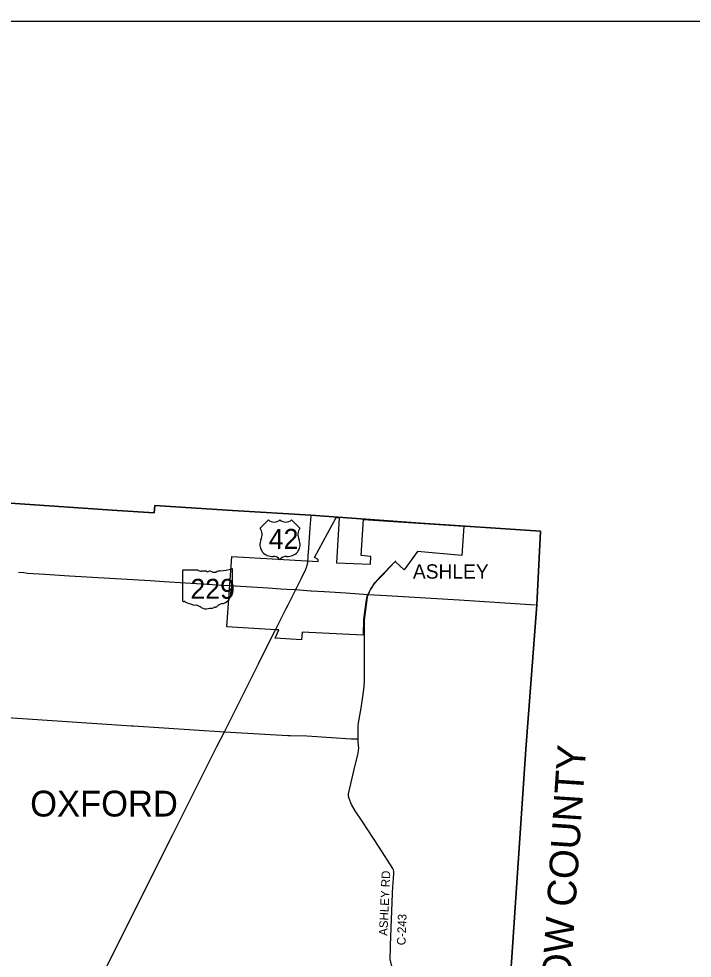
# Model space of a CAD drawing. Extents: x 1674899 to 2057726, y 653888 to 988278.
# Drawn here: x 1831966 to 1855438, y 864966 to 897723 of the extents above; entities that cross this region are included whole.
import ezdxf

# ---------------------------------------------------------------- set-up
doc = ezdxf.new("R2010")
doc.units = 0
for name, color, linetype in [('GM_X_Adjacent_County', 7, 'Continuous'), ('GM_X_Adjacent_County_Text', 7, 'Continuous'), ('GM_X_Corporation', 7, 'Continuous'), ('GM_X_Corporation_Text', 7, 'Continuous'), ('GM_X_County', 7, 'Continuous'), ('GM_X_County_Road', 7, 'Continuous'), ('GM_X_County_Road_Text', 7, 'Continuous'), ('GM_X_State_Location', 7, 'Continuous'), ('GM_X_State_Route', 7, 'Continuous'), ('GM_X_State_Shield', 7, 'Continuous'), ('GM_X_Township', 7, 'Continuous'), ('GM_X_Township_Text', 7, 'Continuous'), ('GM_X_US_Location', 7, 'Continuous'), ('GM_X_US_Route', 7, 'Continuous'), ('GM_X_US_Shield', 7, 'Continuous'), ('SH_Data', 7, 'Continuous'), ('SH_Named_Boundary', 7, 'Continuous')]:
    doc.layers.add(name, color=color, linetype=linetype)

msp = doc.modelspace()

# ---------------------------------------------------------------- linework, layer by layer
at = {"layer": 'GM_X_Adjacent_County'}
msp.add_lwpolyline([(1849106, 864311), (1849634, 872258), (1850017, 877290), (1850147, 879854), (1845959, 880135), (1842150, 880416), (1839410, 880574), (1836708, 880754), (1836682, 880495), (1835395, 880574), (1829123, 881005), (1828513, 881052), (1826517, 881205), (1823082, 881429), (1823458, 886911), (1823627, 889370), (1824025, 895167), (1824431, 901093)], dxfattribs=at)
at = {"layer": 'GM_X_Corporation'}
msp.add_lwpolyline([(1839212, 876522), (1839395, 878979), (1842403, 878797), (1842406, 878874), (1842276, 878944), (1843026, 880333), (1843137, 880326), (1843037, 878758), (1844222, 878701), (1844237, 878976), (1843894, 879006), (1843983, 880269), (1847478, 880034), (1847407, 879013), (1845866, 879149), (1845394, 878513), (1845080, 878796), (1844533, 878238), (1844393, 878064), (1844314, 877970), (1844271, 877898), (1844236, 877846), (1844178, 877730), (1844140, 877653), (1844101, 877578), (1844075, 877468), (1843989, 876865), (1843985, 876781), (1843972, 876227), (1841843, 876336), (1841816, 876073), (1840902, 876121), (1841027, 876414), (1840914, 876421)], close=True, dxfattribs=at)
at = {"layer": 'GM_X_County'}
msp.add_lwpolyline([(1809339, 887629), (1813443, 887429), (1813717, 887422), (1814360, 887388), (1814847, 887358), (1815353, 887328), (1818316, 887169), (1823458, 886911), (1823082, 881429), (1826517, 881205), (1828513, 881052), (1829123, 881005), (1835395, 880574), (1836682, 880495), (1836708, 880754), (1839410, 880574), (1842150, 880416), (1845959, 880135), (1850147, 879854), (1850017, 877290), (1849634, 872258), (1849106, 864311)], dxfattribs=at)
at = {"layer": 'GM_X_County_Road'}
for points in [[(1844140, 877653), (1844178, 877730), (1844236, 877846), (1844271, 877898), (1844314, 877970), (1844393, 878064), (1844672, 878363), (1844876, 878580), (1845108, 878825)], [(1844920, 865421), (1844988, 867215), (1844990, 867274), (1845035, 867925), (1845034, 867981), (1845022, 868042), (1845000, 868095), (1844527, 868834), (1843932, 869740), (1843693, 870106), (1843565, 870325), (1843478, 870530), (1843453, 870621), (1843455, 870702), (1843691, 871703), (1843783, 872054), (1843799, 872125), (1843808, 872218), (1843813, 872294), (1843800, 872513), (1843796, 872610), (1843794, 872719), (1843797, 872872), (1843799, 873058), (1843810, 873171), (1843903, 873683), (1843995, 874339), (1844011, 874603), (1844010, 875790), (1844011, 876128), (1844012, 876758), (1844119, 877561), (1844140, 877653)], [(1825350, 873697), (1828404, 873550), (1830426, 873436), (1830706, 873421), (1835899, 873073), (1835968, 873069), (1839135, 872864)], [(1839135, 872864), (1839344, 872852), (1841345, 872730), (1841421, 872727), (1842003, 872716), (1842870, 872667), (1843552, 872620), (1843796, 872610)], [(1848869, 860822), (1848289, 861017), (1848127, 861070), (1847820, 861177), (1847644, 861252), (1847581, 861290), (1847540, 861317), (1847370, 861450), (1845855, 862679), (1845795, 862727), (1845378, 863132), (1845338, 863172), (1845282, 863256), (1845130, 864033), (1845116, 864109), (1844927, 864878), (1844914, 864930), (1844919, 865353), (1844920, 865421)]]:
    msp.add_lwpolyline(points, dxfattribs=at)
at = {"layer": 'GM_X_State_Route'}
for points in [[(1831957, 878431), (1832136, 878410), (1832267, 878397), (1832870, 878356), (1833733, 878300), (1836550, 878131), (1837033, 878098), (1838904, 877988), (1839306, 877964)], [(1839306, 877964), (1840655, 877877), (1841096, 877846), (1841303, 877834)], [(1841303, 877834), (1841619, 877817)], [(1841619, 877817), (1842011, 877788), (1842144, 877781)], [(1842144, 877781), (1842167, 877780), (1842611, 877751), (1842621, 877751), (1843359, 877702), (1844140, 877653)], [(1844140, 877653), (1844783, 877609), (1847310, 877457), (1849978, 877293)]]:
    msp.add_lwpolyline(points, dxfattribs=at)
at = {"layer": 'GM_X_State_Shield'}
for p, q in [((1837677, 878480), (1837677, 877424)), ((1838204, 878499), (1837694, 878499)), ((1839417, 877972), (1839417, 878525)), ((1839417, 877972), (1839417, 877972))]:
    msp.add_line(p, q, dxfattribs=at)
for centre, major_axis, start_param, end_param in [((1838797, 879939), (1845, 0), 4.814394, 5.042369), ((1839398, 878527), (19.4, 0), 6.141152, 7.989035), ((1837697, 878483), (20.2, 0), 1.712693, 3.28349), ((1838325, 878621), (196, 0), 4.042523, 4.731795), ((1838390, 877905), (702, 0), 1.404758, 1.657858), ((1838549, 878488), (56.4, 0), 3.836095, 5.185415), ((1838632, 878366), (117, 0), 0.950623, 2.079405), ((1838783, 878534), (141, 0), 4.081561, 5.145723), ((1839032, 878176), (371, 0), 1.699011, 2.107814), ((1839413, 877931), (30, 0), 1.883978, 3.671073), ((1839222, 877862), (180, 0), 5.934695, 6.695948), ((1839396, 877970), (20.7, 0), 5.05454, 6.418171), ((1838900, 877670), (462, 0), 5.101752, 6.440018), ((1839486, 877741), (131, 0), 2.387724, 3.262537), ((1837697, 877421), (20.3, 0), 3.00124, 4.508301), ((1837700, 877530), (155, 0), 4.665946, 4.897461), ((1837732, 877363), (56, 0), 0.519207, 1.627899), ((1838438, 878312), (1333, 0), 4.195997, 4.488961), ((1838041, 876949), (417, 0), 0.823519, 1.323587), ((1838775, 877321), (149, 0), 4.937069, 5.64225), ((1839095, 877127), (253, 0), 1.647645, 2.488434), ((1838492, 877358), (265, 0), 4.026481, 4.996735), ((1838645, 876992), (217, 0), 1.495662, 1.94098), ((1838664, 877278), (141, 0), 4.691044, 5.507374), ((1838792, 877176), (39.7, 0), 1.147584, 2.315152)]:
    msp.add_ellipse(centre, major_axis=major_axis, ratio=0.8, start_param=start_param, end_param=end_param, dxfattribs=at)
at = {"layer": 'GM_X_Township'}
msp.add_lwpolyline([(1821956, 864281), (1822382, 871013), (1822583, 873901), (1822822, 877662), (1822932, 879384), (1823026, 880489), (1823082, 881429), (1826517, 881205), (1828513, 881052), (1829123, 881005), (1835395, 880574), (1836682, 880495), (1836708, 880754), (1839410, 880574), (1842150, 880416), (1845959, 880135), (1850147, 879854), (1850017, 877290), (1849634, 872258), (1849106, 864311)], dxfattribs=at)
at = {"layer": 'GM_X_US_Route'}
for points in [[(1842050, 878929), (1842054, 878989), (1842074, 879275), (1842125, 879970), (1842151, 880391)], [(1842000, 878620), (1842005, 878635), (1842013, 878659), (1842035, 878764), (1842042, 878816), (1842050, 878929)], [(1841619, 877817), (1841815, 878219), (1841969, 878528), (1842000, 878620)], [(1841285, 877158), (1841355, 877293), (1841619, 877817)], [(1840905, 876404), (1840914, 876421), (1841039, 876677), (1841285, 877158)], [(1832814, 860270), (1833045, 860728), (1833707, 862039), (1833995, 862623), (1834269, 863162), (1835215, 865051), (1835681, 865996), (1836078, 866774), (1836442, 867502), (1837331, 869279), (1837642, 869882), (1838022, 870648), (1838475, 871555), (1838873, 872351), (1839135, 872864), (1840316, 875226), (1840905, 876404)]]:
    msp.add_lwpolyline(points, dxfattribs=at)
at = {"layer": 'GM_X_US_Shield'}
for p, q in [((1840664, 880255), (1840374, 879965)), ((1841766, 879965), (1841476, 880255)), ((1840780, 878979), (1840838, 878979)), ((1841302, 878979), (1841360, 878979))]:
    msp.add_line(p, q, dxfattribs=at)
for centre, radius, start, end in [((1840867, 880462), 290, 225.573, 314.427), ((1841273, 880462), 290, 225.573, 314.427), ((1840041, 879732), 406, 334.5471, 35.0009), ((1842099, 879732), 406, 144.9991, 205.4529), ((1840775, 879385), 406, 154.8319, 270.6383), ((1841365, 879385), 406, 269.3617, 25.1681), ((1840838, 878689), 290, 36.8699, 90), ((1841302, 878689), 290, 90, 143.1301)]:
    msp.add_arc(centre, radius, start, end, dxfattribs=at)
at = {"layer": 'SH_Data'}
for points in [[(1842050, 878929), (1842054, 878989), (1842074, 879275), (1842125, 879970), (1842151, 880391)], [(1842000, 878620), (1842005, 878635), (1842013, 878659), (1842035, 878764), (1842042, 878816), (1842050, 878929)], [(1841619, 877817), (1841815, 878219), (1841969, 878528), (1842000, 878620)], [(1841285, 877158), (1841355, 877293), (1841619, 877817)], [(1840905, 876404), (1840914, 876421), (1841039, 876677), (1841285, 877158)], [(1832814, 860270), (1833045, 860728), (1833707, 862039), (1833995, 862623), (1834269, 863162), (1835215, 865051), (1835681, 865996), (1836078, 866774), (1836442, 867502), (1837331, 869279), (1837642, 869882), (1838022, 870648), (1838475, 871555), (1838873, 872351), (1839135, 872864), (1840316, 875226), (1840905, 876404)]]:
    msp.add_lwpolyline(points, dxfattribs=at)
at = {"layer": 'SH_Named_Boundary'}
msp.add_lwpolyline([(1741253, 762626), (1916253, 762626), (1916253, 897626), (1741253, 897626)], close=True, dxfattribs=at)

# ---------------------------------------------------------------- texts
at = {"layer": 'GM_X_Adjacent_County_Text'}
msp.add_text('MORROW COUNTY', height=1000, rotation=86.16, dxfattribs=at).set_placement((1850915, 859988))
at = {"layer": 'GM_X_Corporation_Text'}
msp.add_text('ASHLEY', height=500, rotation=0, dxfattribs=at).set_placement((1845704, 878201))
at = {"layer": 'GM_X_County_Road_Text'}
for s, rotation, p in [('ASHLEY RD', 87.4127, (1844815, 865742)), ('C-243', 88.0725, (1845445, 865413))]:
    msp.add_text(s, height=300, rotation=rotation, dxfattribs=at).set_placement(p)
at = {"layer": 'GM_X_State_Location'}
msp.add_text('229', height=1, rotation=0, dxfattribs=at).set_placement((1838174, 877809))
for s in ['s', 'r']:
    msp.add_text(s, height=1, dxfattribs=at).set_placement((1838527, 877882))
at = {"layer": 'GM_X_State_Shield'}
msp.add_text('229', height=696.1, dxfattribs=at).set_placement((1837947, 877498))
at = {"layer": 'GM_X_Township_Text'}
msp.add_text('OXFORD', height=900, rotation=0, dxfattribs=at).set_placement((1832362, 869907))
at = {"layer": 'GM_X_US_Location'}
msp.add_text('42', height=1, rotation=0, dxfattribs=at).set_placement((1841892, 879314))
for s in ['0', '/']:
    msp.add_text(s, height=1, dxfattribs=at).set_placement((1842099, 879521))
at = {"layer": 'GM_X_US_Shield'}
msp.add_text('42', height=696.1, dxfattribs=at).set_placement((1840678, 879240))

doc.saveas('drawing.dxf')
